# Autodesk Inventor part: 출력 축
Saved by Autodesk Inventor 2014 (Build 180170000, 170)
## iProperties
Created: 2025-12
Part Number: 출력 축
Material: 일반
Document SubType Name: Modeling
Designer: dg
Density: 1 g/cm^3
Appearance: 기본값
Author: dg
Author: jhkim
Creation Date: 2025-11-19
Sending System: Autodesk Inventor 2026
Preprocessor: ST-DEVELOPER v20.1
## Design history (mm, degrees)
node "출력 축1"
node "솔리드1"
node "기준1"
